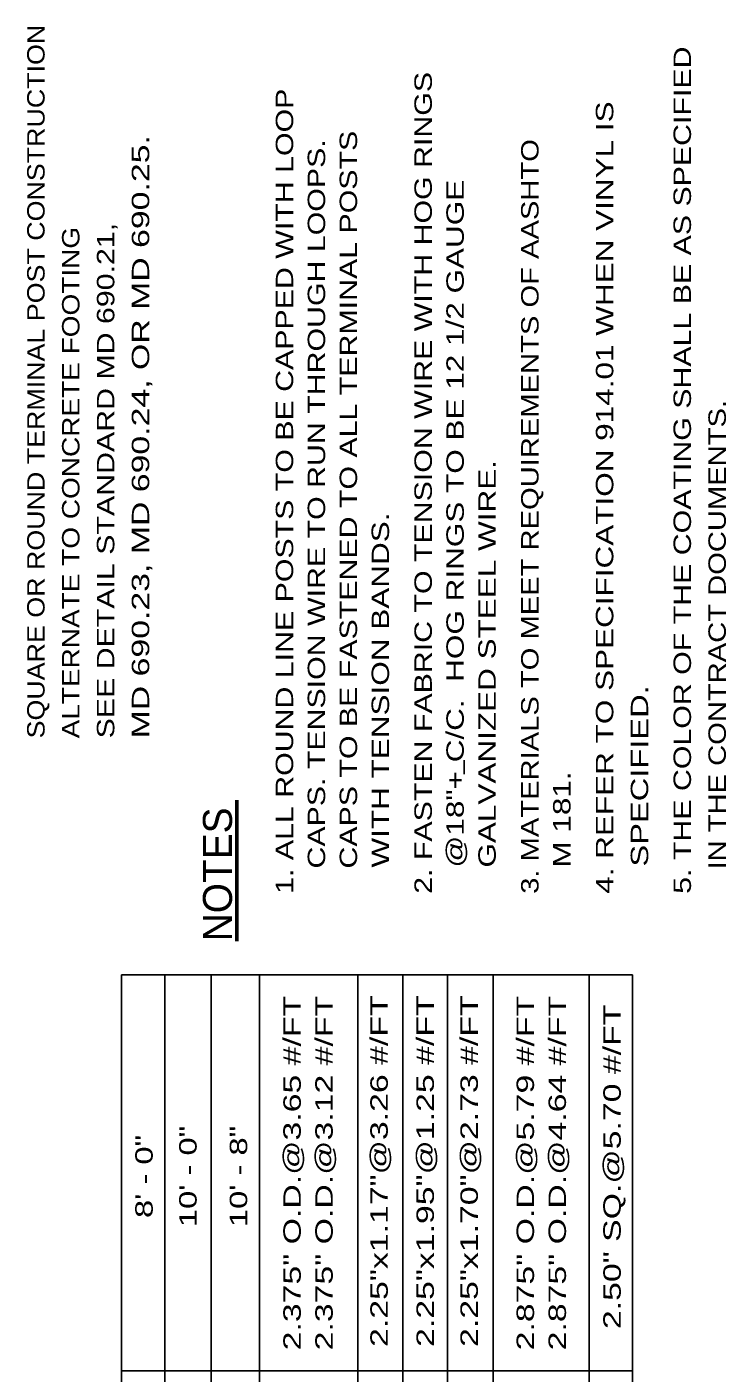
# Model space of a CAD drawing. Extents: x -46.1 to -39.3, y 101.7 to 111.8.
# Drawn here: x -41.664 to -39.257, y 107.135 to 111.767 of the extents above; entities that cross this region are included whole.
import ezdxf
from ezdxf.enums import TextEntityAlignment as Align

# ---------------------------------------------------------------- set-up
doc = ezdxf.new("R2010")
doc.units = 0
doc.header["$LTSCALE"] = 0.024
doc.layers.add('12', color=7, linetype='Continuous', lineweight=53)
doc.layers.add('13', color=7, linetype='Continuous', lineweight=25)

msp = doc.modelspace()

# ---------------------------------------------------------------- linework, layer by layer
at = {"layer": '13'}
for p, q in [((-40.15846, 109.19515), (-40.15846, 109.24352)), ((-41.33798, 103.13735), (-41.33798, 108.50462)), ((-39.57975, 108.50462), (-41.33798, 108.50462)), ((-41.18894, 103.13735), (-41.18894, 108.50462)), ((-41.02979, 103.13735), (-41.02979, 108.50462)), ((-40.86306, 103.13735), (-40.86306, 108.50462)), ((-40.52454, 103.54608), (-40.52454, 108.50462)), ((-40.37044, 103.54608), (-40.37044, 108.50462)), ((-40.21635, 103.54608), (-40.21635, 108.50462)), ((-40.05973, 103.13735), (-40.05973, 108.50462)), ((-39.72879, 103.54608), (-39.72879, 108.50462)), ((-39.57975, 103.13735), (-39.57975, 108.50462)), ((-39.57975, 107.14202), (-41.33798, 107.14202))]:
    msp.add_line(p, q, dxfattribs=at)
at = {"layer": '13', "lineweight": 53}
msp.add_line((-40.94106, 108.62033), (-40.94106, 109.1059), dxfattribs=at)

# ---------------------------------------------------------------- texts
at = {"layer": '12'}
for s, width, p in [('SQUARE OR ROUND TERMINAL POST CONSTRUCTION', 1.15, (-41.60314, 109.31862)), ('MD 690.23, MD 690.24, OR MD 690.25.', 1.45, (-41.24314, 109.31862)), ('SEE DETAIL STANDARD MD 690.21,', 1.3, (-41.36314, 109.31862)), ('ALTERNATE TO CONCRETE FOOTING', 1.2, (-41.48314, 109.31862))]:
    msp.add_text(s, height=0.06, rotation=90, dxfattribs=dict(at, width=width)).set_placement(p)
at = {"layer": '13'}
for s, width, p in [('5. THE COLOR OF THE COATING SHALL BE AS SPECIFIED', 1.3, (-39.37834, 108.78383)), ('2. FASTEN FABRIC TO TENSION WIRE WITH HOG RINGS', 1.3, (-40.27025, 108.78383)), ('1. ALL ROUND LINE POSTS TO BE CAPPED WITH LOOP', 1.3, (-40.74755, 108.78383)), ('4. REFER TO SPECIFICATION 914.01 WHEN VINYL IS', 1.35, (-39.64565, 108.78383)), ('   CAPS TO BE FASTENED TO ALL TERMINAL POSTS', 1.3, (-40.52755, 108.78383)), ('   CAPS. TENSION WIRE TO RUN THROUGH LOOPS.', 1.3, (-40.63755, 108.78383)), ('3. MATERIALS TO MEET REQUIREMENTS OF AASHTO', 1.25, (-39.90295, 108.78383)), ('   @18"+ C/C.  HOG RINGS TO BE 12 1/2 GAUGE', 1.35, (-40.16025, 108.78383)), ('   IN THE CONTRACT DOCUMENTS.', 1.25, (-39.25834, 108.78383)), ('   GALVANIZED STEEL WIRE.', 1.35, (-40.05025, 108.78383)), ('   WITH TENSION BANDS.', 1.35, (-40.41755, 108.78383)), ('   SPECIFIED.', 1.4, (-39.52565, 108.78383)), ('   M 181.', 1.35, (-39.79295, 108.78383))]:
    msp.add_text(s, height=0.06, rotation=90, dxfattribs=dict(at, width=width)).set_placement(p)
msp.add_text('NOTES', height=0.1, rotation=90, dxfattribs=at).set_placement((-40.95816, 108.62032))
for s, rotation, width, p in [('2.25"x1.17"@3.26 #/FT', 90.002, 1.45, (-40.42193, 107.82953)), ('2.25"x1.95"@1.25 #/FT', 90.002, 1.45, (-40.26313, 107.82953)), ('2.25"x1.70"@2.73 #/FT', 90.002, 1.45, (-40.11189, 107.82953)), ('2.375" O.D.@3.65 #/FT', 90.002, 1.45, (-40.72143, 107.82288)), ('2.375" O.D.@3.12 #/FT', 90.002, 1.45, (-40.61143, 107.82289)), ('2.875" O.D.@5.79 #/FT', 90.002, 1.45, (-39.91863, 107.82288)), ('2.875" O.D.@4.64 #/FT', 90.002, 1.45, (-39.80863, 107.82288)), ('2.50" SQ.@5.70 #/FT', 90, 1.45, (-39.62005, 107.84437)), ('10\' - 0"', 90.002, 1.4, (-41.07982, 107.81143)), ('10\' - 8"', 90.002, 1.4, (-40.90589, 107.81143)), ('8\' - 0"', 90.002, 1.4, (-41.23106, 107.81142))]:
    msp.add_text(s, height=0.06, rotation=rotation, dxfattribs=dict(at, width=width)).set_placement(p, align=Align.CENTER)

doc.saveas('drawing.dxf')
